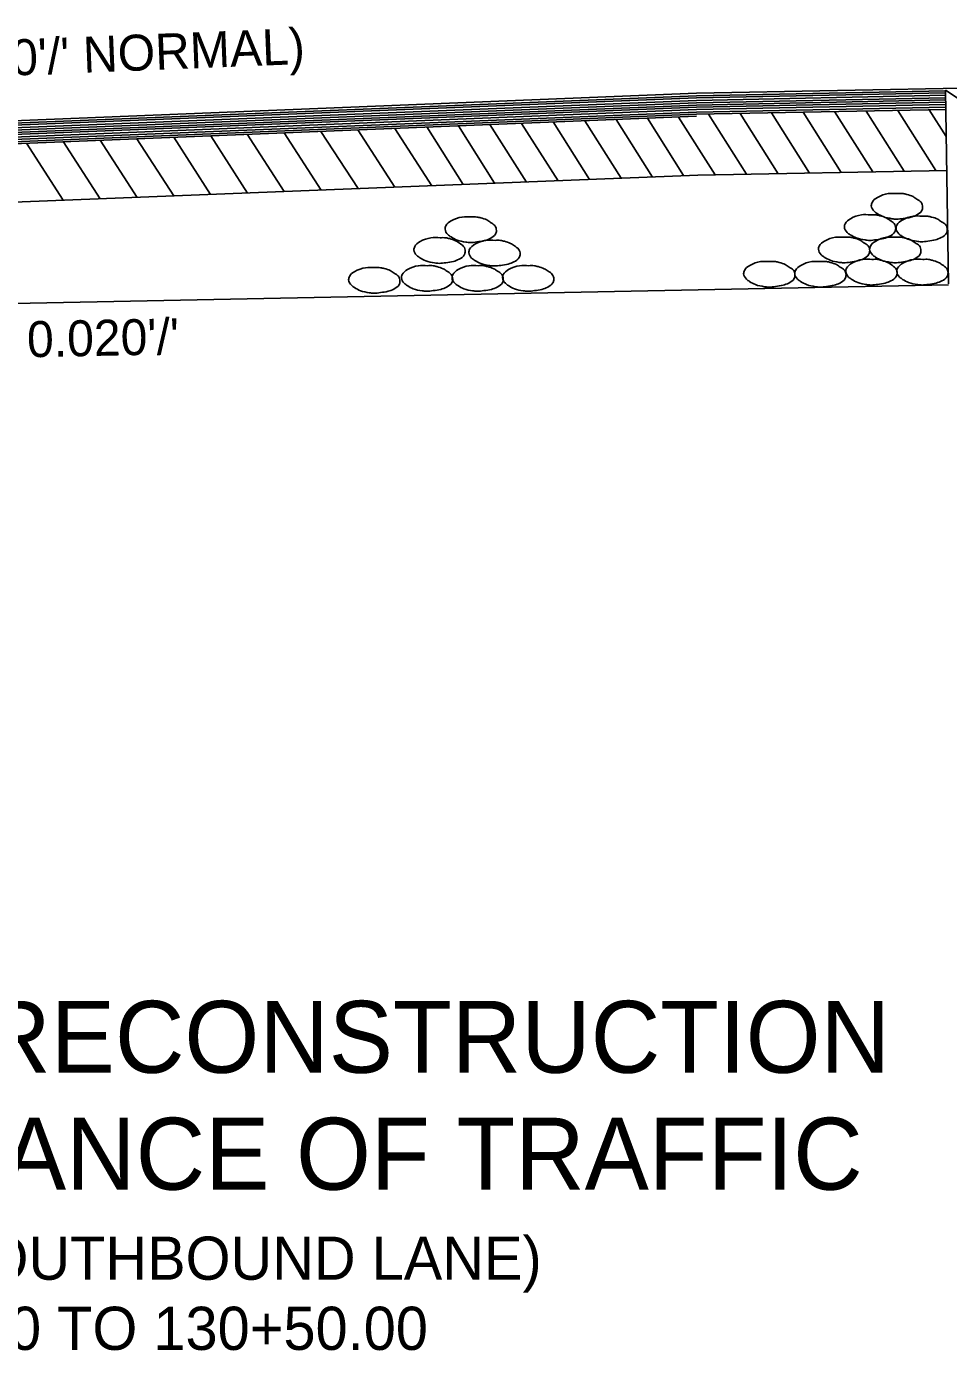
# Model space of a CAD drawing. Extents: x 634177 to 635904, y 289936 to 290970.
# Drawn here: x 635664.86 to 635680.23, y 290759.69 to 290781.78 of the extents above; entities that cross this region are included whole.
import ezdxf

# ---------------------------------------------------------------- set-up
doc = ezdxf.new("R2010")
doc.units = 0
doc.layers.add('Default', color=7, linetype='Continuous')

msp = doc.modelspace()

# ---------------------------------------------------------------- linework, layer by layer
at = {"layer": 'Default'}
for p, q in [((635695.808, 290781.054), (635676.031, 290780.665)), ((635676.031, 290780.588), (635657.761, 290779.858)), ((635676.031, 290780.621), (635657.78, 290779.887)), ((635676.031, 290780.665), (635657.808, 290779.932)), ((635680.18, 290780.704), (635676.031, 290780.621)), ((635680.181, 290780.671), (635676.031, 290780.588)), ((635680.181, 290780.63), (635676.031, 290780.546)), ((635680.182, 290780.589), (635676.031, 290780.504)), ((635680.182, 290780.552), (635676.031, 290780.468)), ((635680.18, 290780.715), (635680.231, 290777.483)), ((635676.031, 290780.35), (635657.602, 290779.61)), ((635676.031, 290780.392), (635657.626, 290779.65)), ((635676.031, 290780.43), (635657.658, 290779.694)), ((635676.031, 290780.468), (635657.68, 290779.728)), ((635676.031, 290780.504), (635657.708, 290779.772)), ((635676.031, 290780.546), (635657.73, 290779.812)), ((635680.183, 290780.513), (635676.031, 290780.43)), ((635680.184, 290780.475), (635676.031, 290780.392)), ((635680.184, 290780.432), (635676.031, 290780.35)), ((635680.185, 290780.394), (635676.031, 290780.313)), ((635677.915, 290779.333), (635677.281, 290780.337)), ((635678.441, 290779.344), (635677.807, 290780.348)), ((635678.967, 290779.354), (635678.332, 290780.358)), ((635679.493, 290779.364), (635678.858, 290780.368)), ((635680.018, 290779.375), (635679.384, 290780.379)), ((635680.192, 290779.942), (635679.91, 290780.389)), ((635676.031, 290780.28), (635657.559, 290779.538)), ((635676.031, 290780.313), (635657.576, 290779.566)), ((635672.662, 290779.163), (635672.059, 290780.121)), ((635673.192, 290779.184), (635672.585, 290780.144)), ((635673.72, 290779.205), (635673.11, 290780.161)), ((635674.246, 290779.226), (635673.638, 290780.187)), ((635674.772, 290779.247), (635674.164, 290780.207)), ((635675.296, 290779.267), (635674.688, 290780.229)), ((635675.812, 290779.292), (635675.209, 290780.247)), ((635676.338, 290779.302), (635675.728, 290780.268)), ((635676.864, 290779.313), (635676.229, 290780.317)), ((635677.389, 290779.323), (635676.755, 290780.327)), ((635667.311, 290778.952), (635666.698, 290779.904)), ((635667.926, 290778.976), (635667.312, 290779.931)), ((635668.542, 290779), (635667.928, 290779.954)), ((635669.152, 290779.024), (635668.537, 290779.981)), ((635669.771, 290779.049), (635669.154, 290780.006)), ((635670.385, 290779.074), (635669.765, 290780.029)), ((635671, 290779.097), (635670.383, 290780.052)), ((635671.616, 290779.122), (635670.997, 290780.077)), ((635672.138, 290779.142), (635671.532, 290780.102)), ((635665.47, 290778.879), (635664.858, 290779.834)), ((635666.082, 290778.903), (635665.467, 290779.859)), ((635666.703, 290778.927), (635666.084, 290779.881)), ((635676.051, 290779.297), (635656.926, 290778.542)), ((635680.201, 290779.378), (635676.051, 290779.297)), ((635680.231, 290777.471), (635635.348, 290776.574))]:
    msp.add_line(p, q, dxfattribs=at)
msp.add_lwpolyline([(635680.18, 290780.715), (635684.121, 290778.09)], dxfattribs=at)
for points in [[(635679.38, 290778.991), (635679.227, 290778.99), (635679.045, 290778.926), (635678.956, 290778.843), (635678.944, 290778.789), (635678.99, 290778.697), (635679.042, 290778.658), (635679.142, 290778.606), (635679.288, 290778.572), (635679.364, 290778.564), (635679.475, 290778.575), (635679.601, 290778.596), (635679.696, 290778.633), (635679.784, 290778.706), (635679.799, 290778.764), (635679.773, 290778.846), (635679.703, 290778.899), (635679.639, 290778.941), (635679.537, 290778.976), (635679.474, 290778.99), (635679.38, 290778.991)], [(635672.273, 290778.601), (635672.12, 290778.6), (635671.938, 290778.536), (635671.849, 290778.453), (635671.837, 290778.399), (635671.883, 290778.307), (635671.935, 290778.268), (635672.035, 290778.216), (635672.181, 290778.182), (635672.257, 290778.174), (635672.368, 290778.185), (635672.494, 290778.206), (635672.589, 290778.243), (635672.677, 290778.316), (635672.692, 290778.374), (635672.666, 290778.456), (635672.596, 290778.509), (635672.532, 290778.551), (635672.43, 290778.586), (635672.367, 290778.6), (635672.273, 290778.601)], [(635678.931, 290778.637), (635678.778, 290778.636), (635678.596, 290778.572), (635678.507, 290778.489), (635678.495, 290778.435), (635678.541, 290778.343), (635678.593, 290778.304), (635678.693, 290778.252), (635678.839, 290778.218), (635678.915, 290778.21), (635679.026, 290778.221), (635679.152, 290778.242), (635679.247, 290778.279), (635679.335, 290778.352), (635679.35, 290778.41), (635679.324, 290778.492), (635679.254, 290778.545), (635679.19, 290778.587), (635679.088, 290778.622), (635679.025, 290778.636), (635678.931, 290778.637)], [(635679.792, 290778.614), (635679.639, 290778.613), (635679.457, 290778.549), (635679.368, 290778.466), (635679.356, 290778.412), (635679.402, 290778.32), (635679.454, 290778.281), (635679.554, 290778.229), (635679.7, 290778.195), (635679.776, 290778.187), (635679.887, 290778.198), (635680.013, 290778.219), (635680.108, 290778.256), (635680.196, 290778.329), (635680.211, 290778.387), (635680.185, 290778.469), (635680.115, 290778.522), (635680.051, 290778.564), (635679.949, 290778.599), (635679.886, 290778.613), (635679.792, 290778.614)], [(635671.753, 290778.254), (635671.6, 290778.253), (635671.418, 290778.189), (635671.329, 290778.106), (635671.317, 290778.052), (635671.363, 290777.96), (635671.415, 290777.921), (635671.515, 290777.869), (635671.661, 290777.835), (635671.737, 290777.827), (635671.848, 290777.838), (635671.974, 290777.859), (635672.069, 290777.896), (635672.157, 290777.969), (635672.172, 290778.027), (635672.146, 290778.109), (635672.076, 290778.162), (635672.012, 290778.204), (635671.91, 290778.239), (635671.847, 290778.253), (635671.753, 290778.254)], [(635672.669, 290778.21), (635672.516, 290778.209), (635672.334, 290778.145), (635672.245, 290778.062), (635672.233, 290778.008), (635672.279, 290777.916), (635672.331, 290777.877), (635672.431, 290777.825), (635672.577, 290777.791), (635672.653, 290777.783), (635672.764, 290777.794), (635672.89, 290777.815), (635672.985, 290777.852), (635673.073, 290777.925), (635673.088, 290777.983), (635673.062, 290778.065), (635672.992, 290778.118), (635672.928, 290778.16), (635672.826, 290778.195), (635672.763, 290778.209), (635672.669, 290778.21)], [(635678.498, 290778.263), (635678.345, 290778.262), (635678.163, 290778.198), (635678.074, 290778.115), (635678.062, 290778.061), (635678.108, 290777.969), (635678.16, 290777.93), (635678.26, 290777.878), (635678.406, 290777.844), (635678.482, 290777.836), (635678.593, 290777.847), (635678.719, 290777.868), (635678.814, 290777.905), (635678.902, 290777.978), (635678.917, 290778.036), (635678.891, 290778.118), (635678.821, 290778.171), (635678.757, 290778.213), (635678.655, 290778.248), (635678.592, 290778.262), (635678.498, 290778.263)], [(635679.352, 290778.263), (635679.199, 290778.262), (635679.017, 290778.198), (635678.928, 290778.115), (635678.916, 290778.061), (635678.962, 290777.969), (635679.014, 290777.93), (635679.114, 290777.878), (635679.26, 290777.844), (635679.336, 290777.836), (635679.447, 290777.847), (635679.573, 290777.868), (635679.668, 290777.905), (635679.756, 290777.978), (635679.771, 290778.036), (635679.745, 290778.118), (635679.675, 290778.171), (635679.611, 290778.213), (635679.509, 290778.248), (635679.446, 290778.262), (635679.352, 290778.263)], [(635678.955, 290777.893), (635678.802, 290777.892), (635678.62, 290777.828), (635678.531, 290777.745), (635678.519, 290777.691), (635678.565, 290777.599), (635678.617, 290777.56), (635678.717, 290777.508), (635678.863, 290777.474), (635678.939, 290777.466), (635679.05, 290777.477), (635679.176, 290777.498), (635679.271, 290777.535), (635679.359, 290777.608), (635679.374, 290777.666), (635679.348, 290777.748), (635679.278, 290777.801), (635679.214, 290777.843), (635679.112, 290777.878), (635679.049, 290777.892), (635678.955, 290777.893)], [(635679.804, 290777.893), (635679.651, 290777.892), (635679.469, 290777.828), (635679.38, 290777.745), (635679.368, 290777.691), (635679.414, 290777.599), (635679.466, 290777.56), (635679.566, 290777.508), (635679.712, 290777.474), (635679.788, 290777.466), (635679.899, 290777.477), (635680.025, 290777.498), (635680.12, 290777.535), (635680.208, 290777.608), (635680.223, 290777.666), (635680.197, 290777.748), (635680.127, 290777.801), (635680.063, 290777.843), (635679.961, 290777.878), (635679.898, 290777.892), (635679.804, 290777.893)], [(635670.664, 290777.756), (635670.511, 290777.755), (635670.329, 290777.691), (635670.24, 290777.608), (635670.228, 290777.554), (635670.274, 290777.462), (635670.326, 290777.423), (635670.426, 290777.371), (635670.572, 290777.337), (635670.648, 290777.329), (635670.759, 290777.34), (635670.885, 290777.361), (635670.98, 290777.398), (635671.068, 290777.471), (635671.083, 290777.529), (635671.057, 290777.611), (635670.987, 290777.664), (635670.923, 290777.706), (635670.821, 290777.741), (635670.758, 290777.755), (635670.664, 290777.756)], [(635671.544, 290777.788), (635671.391, 290777.787), (635671.209, 290777.723), (635671.12, 290777.64), (635671.108, 290777.586), (635671.154, 290777.494), (635671.206, 290777.455), (635671.306, 290777.403), (635671.452, 290777.369), (635671.528, 290777.361), (635671.639, 290777.372), (635671.765, 290777.393), (635671.86, 290777.43), (635671.948, 290777.503), (635671.963, 290777.561), (635671.937, 290777.643), (635671.867, 290777.696), (635671.803, 290777.738), (635671.701, 290777.773), (635671.638, 290777.787), (635671.544, 290777.788)], [(635672.388, 290777.788), (635672.235, 290777.787), (635672.053, 290777.723), (635671.964, 290777.64), (635671.952, 290777.586), (635671.998, 290777.494), (635672.05, 290777.455), (635672.15, 290777.403), (635672.296, 290777.369), (635672.372, 290777.361), (635672.483, 290777.372), (635672.609, 290777.393), (635672.704, 290777.43), (635672.792, 290777.503), (635672.807, 290777.561), (635672.781, 290777.643), (635672.711, 290777.696), (635672.647, 290777.738), (635672.545, 290777.773), (635672.482, 290777.787), (635672.388, 290777.788)], [(635673.231, 290777.788), (635673.078, 290777.787), (635672.896, 290777.723), (635672.807, 290777.64), (635672.795, 290777.586), (635672.841, 290777.494), (635672.893, 290777.455), (635672.993, 290777.403), (635673.139, 290777.369), (635673.215, 290777.361), (635673.326, 290777.372), (635673.452, 290777.393), (635673.547, 290777.43), (635673.635, 290777.503), (635673.65, 290777.561), (635673.624, 290777.643), (635673.554, 290777.696), (635673.49, 290777.738), (635673.388, 290777.773), (635673.325, 290777.787), (635673.231, 290777.788)], [(635677.251, 290777.857), (635677.098, 290777.856), (635676.916, 290777.792), (635676.827, 290777.709), (635676.815, 290777.655), (635676.861, 290777.563), (635676.913, 290777.524), (635677.013, 290777.472), (635677.159, 290777.438), (635677.235, 290777.43), (635677.346, 290777.441), (635677.472, 290777.462), (635677.567, 290777.499), (635677.655, 290777.572), (635677.67, 290777.63), (635677.644, 290777.712), (635677.574, 290777.765), (635677.51, 290777.807), (635677.408, 290777.842), (635677.345, 290777.856), (635677.251, 290777.857)], [(635678.103, 290777.857), (635677.95, 290777.856), (635677.768, 290777.792), (635677.679, 290777.709), (635677.667, 290777.655), (635677.713, 290777.563), (635677.765, 290777.524), (635677.865, 290777.472), (635678.011, 290777.438), (635678.087, 290777.43), (635678.198, 290777.441), (635678.324, 290777.462), (635678.419, 290777.499), (635678.507, 290777.572), (635678.522, 290777.63), (635678.496, 290777.712), (635678.426, 290777.765), (635678.362, 290777.807), (635678.26, 290777.842), (635678.197, 290777.856), (635678.103, 290777.857)]]:
    msp.add_spline(points, degree=3, dxfattribs=at)

# ---------------------------------------------------------------- texts
for s, rotation, p in [("VAR. (0.040'/' NORMAL)", 2.2923, (635660.691, 290780.801)), ("0.020'/'", 1.1457, (635664.87, 290776.26))]:
    msp.add_text(s, height=0.6, rotation=rotation, dxfattribs=at).set_placement(p)
for s, height, p in [('SHOULDER RECONSTRUCTION', 1.2, (635654.739, 290764.326)), ('FOR MAINTENANCE OF TRAFFIC', 1.2, (635653.393, 290762.376)), ('HWY. 71 (SOUTHBOUND LANE)', 0.72, (635659.057, 290760.874)), ('STA. 99+50.00 TO 130+50.00', 0.72, (635658.65, 290759.704))]:
    msp.add_text(s, height=height, dxfattribs=at).set_placement(p)

doc.saveas('drawing.dxf')
